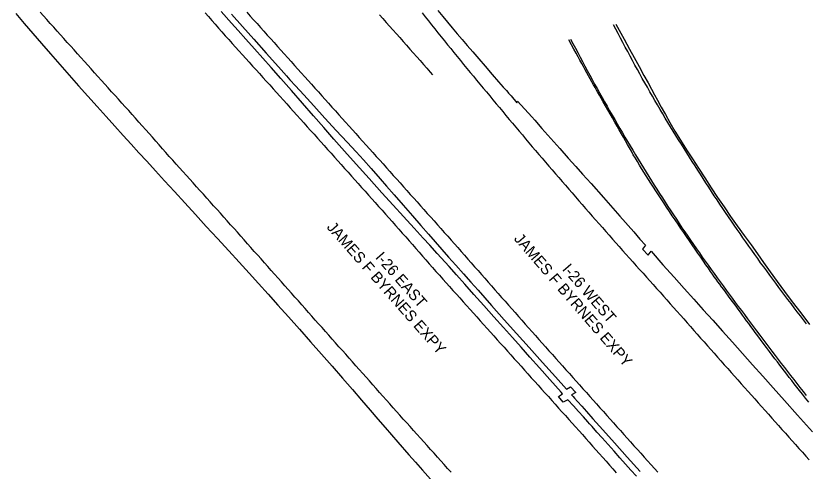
# Model space of a CAD drawing. Extents: x 1948091 to 1975253, y 787267 to 823306.
# Drawn here: x 1967304 to 1967691, y 800434.1 to 800657.3 of the extents above; entities that cross this region are included whole.
import ezdxf

# ---------------------------------------------------------------- set-up
doc = ezdxf.new("R2010")
doc.units = 0
for name, color, linetype in [('RD_EX_Pavement_Markings', 7, 'Continuous'), ('RD_EX_Road', 7, 'Continuous'), ('RD_TX_RoadID', 7, 'Continuous')]:
    doc.layers.add(name, color=color, linetype=linetype)

msp = doc.modelspace()

# ---------------------------------------------------------------- linework, layer by layer
at = {"layer": 'RD_EX_Pavement_Markings'}
for points in [[(1967517.07, 800433.59), (1967515.4, 800435.45), (1967513.73, 800437.31), (1967512.06, 800439.16), (1967510.39, 800441.02), (1967508.73, 800442.88), (1967507.06, 800444.74), (1967505.39, 800446.6), (1967503.72, 800448.46), (1967502.05, 800450.32), (1967500.38, 800452.17), (1967498.71, 800454.03), (1967497.04, 800455.89), (1967495.38, 800457.75), (1967493.71, 800459.61), (1967492.04, 800461.47), (1967490.37, 800463.33), (1967488.71, 800465.19), (1967487.06, 800467.06), (1967485.4, 800468.93), (1967483.74, 800470.8), (1967482.08, 800472.67), (1967480.43, 800474.54), (1967478.77, 800476.41), (1967477.11, 800478.28), (1967475.45, 800480.14), (1967473.8, 800482.01), (1967472.14, 800483.88), (1967470.48, 800485.75), (1967468.82, 800487.62), (1967467.17, 800489.49), (1967465.51, 800491.36), (1967463.85, 800493.22), (1967462.19, 800495.09), (1967460.53, 800496.96), (1967458.88, 800498.83), (1967457.22, 800500.7), (1967455.56, 800502.57), (1967453.9, 800504.43), (1967452.25, 800506.3), (1967450.59, 800508.17), (1967448.93, 800510.04), (1967447.27, 800511.91), (1967445.61, 800513.78), (1967443.96, 800515.64), (1967442.3, 800517.51), (1967440.64, 800519.38), (1967438.98, 800521.25), (1967437.32, 800523.12), (1967435.67, 800524.99), (1967434.01, 800526.85), (1967432.35, 800528.72), (1967430.69, 800530.59), (1967429.04, 800532.46), (1967427.38, 800534.33), (1967425.72, 800536.2), (1967424.06, 800538.07), (1967422.41, 800539.93), (1967420.75, 800541.8), (1967419.09, 800543.67), (1967417.43, 800545.54), (1967415.78, 800547.41), (1967414.12, 800549.28), (1967412.46, 800551.15), (1967410.8, 800553.01), (1967409.14, 800554.88), (1967407.49, 800556.75), (1967405.83, 800558.62), (1967404.17, 800560.49), (1967402.5, 800562.34), (1967400.83, 800564.2), (1967399.16, 800566.06), (1967397.48, 800567.91), (1967395.81, 800569.77), (1967394.14, 800571.63), (1967392.47, 800573.49), (1967390.8, 800575.34), (1967389.13, 800577.2), (1967387.46, 800579.06), (1967385.79, 800580.91), (1967384.12, 800582.77), (1967382.45, 800584.63), (1967380.78, 800586.49), (1967379.11, 800588.35), (1967377.46, 800590.22), (1967375.81, 800592.1), (1967374.15, 800593.97), (1967372.5, 800595.84), (1967370.85, 800597.72), (1967369.2, 800599.59), (1967367.55, 800601.46), (1967365.89, 800603.34), (1967364.24, 800605.21), (1967362.58, 800607.08), (1967360.91, 800608.93), (1967359.23, 800610.79), (1967357.56, 800612.64), (1967355.89, 800614.5), (1967354.21, 800616.35), (1967352.54, 800618.21), (1967350.87, 800620.07), (1967349.2, 800621.92), (1967347.52, 800623.78), (1967345.85, 800625.63), (1967344.18, 800627.49), (1967342.51, 800629.34), (1967340.84, 800631.21), (1967339.17, 800633.07), (1967337.51, 800634.93), (1967335.84, 800636.79), (1967334.17, 800638.65), (1967332.51, 800640.51), (1967330.84, 800642.37), (1967329.17, 800644.23), (1967327.51, 800646.1), (1967325.84, 800647.96), (1967324.17, 800649.82), (1967322.51, 800651.68), (1967320.84, 800653.54), (1967319.17, 800655.39), (1967317.49, 800657.25), (1967315.82, 800659.11)], [(1967396.61, 800658.72), (1967398.26, 800656.85), (1967399.92, 800654.99), (1967401.58, 800653.12), (1967403.24, 800651.25), (1967404.89, 800649.38), (1967406.55, 800647.51), (1967408.21, 800645.64), (1967409.87, 800643.77), (1967411.53, 800641.91), (1967413.21, 800640.06), (1967414.88, 800638.2), (1967416.56, 800636.35), (1967418.23, 800634.49), (1967419.9, 800632.64), (1967421.58, 800630.79), (1967423.25, 800628.93), (1967424.93, 800627.08), (1967426.6, 800625.22), (1967428.28, 800623.37), (1967429.95, 800621.51), (1967431.62, 800619.66), (1967433.3, 800617.8), (1967434.96, 800615.94), (1967436.63, 800614.09), (1967438.3, 800612.23), (1967439.97, 800610.37), (1967441.64, 800608.51), (1967443.31, 800606.65), (1967444.97, 800604.79), (1967446.64, 800602.93), (1967448.31, 800601.07), (1967449.98, 800599.21), (1967451.65, 800597.35), (1967453.31, 800595.49), (1967454.98, 800593.63), (1967456.65, 800591.77), (1967458.32, 800589.91), (1967459.98, 800588.05), (1967461.65, 800586.19), (1967463.31, 800584.33), (1967464.98, 800582.46), (1967466.64, 800580.6), (1967468.31, 800578.74), (1967469.97, 800576.88), (1967471.64, 800575.01), (1967473.3, 800573.15), (1967474.97, 800571.29), (1967476.63, 800569.43), (1967478.29, 800567.57), (1967479.96, 800565.7), (1967481.62, 800563.84), (1967483.29, 800561.98), (1967484.95, 800560.12), (1967486.61, 800558.25), (1967488.26, 800556.37), (1967489.91, 800554.5), (1967491.56, 800552.62), (1967493.21, 800550.74), (1967494.86, 800548.87), (1967496.51, 800546.99), (1967498.15, 800545.11), (1967499.8, 800543.24), (1967501.45, 800541.36), (1967503.1, 800539.49), (1967504.75, 800537.61), (1967506.4, 800535.73), (1967508.05, 800533.86), (1967509.7, 800531.98), (1967511.36, 800530.12), (1967513.03, 800528.26), (1967514.7, 800526.4), (1967516.36, 800524.54), (1967518.03, 800522.68), (1967519.7, 800520.82), (1967521.36, 800518.96), (1967523.03, 800517.1), (1967524.7, 800515.24), (1967526.36, 800513.37), (1967528.03, 800511.51), (1967529.7, 800509.65), (1967531.36, 800507.79), (1967533.03, 800505.93), (1967534.7, 800504.07), (1967536.37, 800502.21), (1967538.03, 800500.35), (1967539.7, 800498.5), (1967541.37, 800496.64), (1967543.04, 800494.78), (1967544.7, 800492.92), (1967546.37, 800491.06), (1967548.04, 800489.2), (1967549.71, 800487.34), (1967551.37, 800485.48), (1967553.04, 800483.62), (1967554.71, 800481.76), (1967556.38, 800479.9), (1967558.05, 800478.04), (1967559.71, 800476.18), (1967561.38, 800474.32), (1967563.05, 800472.46), (1967564.72, 800470.6), (1967566.39, 800468.74), (1967568.05, 800466.88), (1967569.72, 800465.02), (1967571.39, 800463.16), (1967573.06, 800461.3), (1967574.73, 800459.44), (1967576.39, 800457.59), (1967578.06, 800455.73), (1967579.73, 800453.86), (1967581.38, 800451.99), (1967583.04, 800450.13), (1967584.7, 800448.26), (1967586.36, 800446.39), (1967588.02, 800444.53), (1967589.68, 800442.66), (1967591.34, 800440.79), (1967593, 800438.92), (1967594.66, 800437.06), (1967596.32, 800435.19), (1967597.97, 800433.32)], [(1967417.08, 800659.03), (1967418.74, 800657.16), (1967420.41, 800655.3), (1967422.08, 800653.44), (1967423.75, 800651.58), (1967425.41, 800649.72), (1967427.08, 800647.86), (1967428.75, 800646), (1967430.41, 800644.14), (1967432.08, 800642.28), (1967433.75, 800640.42), (1967435.42, 800638.56), (1967437.08, 800636.7), (1967438.75, 800634.84), (1967440.42, 800632.98), (1967442.08, 800631.12), (1967443.75, 800629.25), (1967445.42, 800627.4), (1967447.09, 800625.54), (1967448.76, 800623.68), (1967450.42, 800621.82), (1967452.09, 800619.96), (1967453.76, 800618.1), (1967455.43, 800616.24), (1967457.1, 800614.38), (1967458.77, 800612.52), (1967460.43, 800610.66), (1967462.1, 800608.8), (1967463.77, 800606.94), (1967465.44, 800605.08), (1967467.11, 800603.22), (1967468.78, 800601.37), (1967470.45, 800599.51), (1967472.11, 800597.65), (1967473.78, 800595.79), (1967475.45, 800593.93), (1967477.12, 800592.07), (1967478.79, 800590.21), (1967480.46, 800588.35), (1967482.13, 800586.49), (1967483.8, 800584.64), (1967485.46, 800582.78), (1967487.13, 800580.92), (1967488.8, 800579.06), (1967490.47, 800577.2), (1967492.14, 800575.34), (1967493.8, 800573.48), (1967495.47, 800571.62), (1967497.13, 800569.76), (1967498.8, 800567.9), (1967500.47, 800566.03), (1967502.13, 800564.17), (1967503.8, 800562.31), (1967505.46, 800560.45), (1967507.13, 800558.59), (1967508.8, 800556.73), (1967510.46, 800554.87), (1967512.13, 800553.01), (1967513.78, 800551.13), (1967515.43, 800549.26), (1967517.08, 800547.38), (1967518.73, 800545.51), (1967520.38, 800543.63), (1967522.03, 800541.76), (1967523.68, 800539.88), (1967525.33, 800538.01), (1967526.98, 800536.13), (1967528.63, 800534.25), (1967530.28, 800532.38), (1967531.93, 800530.5), (1967533.58, 800528.63), (1967535.23, 800526.75), (1967536.88, 800524.88), (1967538.54, 800523.01), (1967540.19, 800521.14), (1967541.84, 800519.27), (1967543.5, 800517.39), (1967545.15, 800515.52), (1967546.81, 800513.65), (1967548.46, 800511.78), (1967550.11, 800509.9), (1967551.77, 800508.03), (1967553.42, 800506.16), (1967555.07, 800504.29), (1967556.73, 800502.42), (1967558.38, 800500.54), (1967560.03, 800498.67), (1967561.7, 800496.81), (1967563.36, 800494.94), (1967565.02, 800493.08), (1967566.69, 800491.22), (1967568.35, 800489.36), (1967570.02, 800487.49), (1967571.68, 800485.63), (1967573.35, 800483.77), (1967575.01, 800481.91), (1967576.68, 800480.04), (1967578.34, 800478.18), (1967580.01, 800476.32), (1967581.67, 800474.46), (1967583.34, 800472.59), (1967585, 800470.73), (1967586.66, 800468.87), (1967588.33, 800467.01), (1967589.99, 800465.14), (1967591.66, 800463.28), (1967593.32, 800461.42), (1967594.99, 800459.56), (1967596.65, 800457.69), (1967598.32, 800455.83), (1967599.98, 800453.97), (1967601.65, 800452.11), (1967603.32, 800450.25), (1967604.99, 800448.4), (1967606.66, 800446.54), (1967608.33, 800444.68), (1967610, 800442.83), (1967611.68, 800440.97), (1967613.35, 800439.12), (1967615.02, 800437.26), (1967616.69, 800435.4), (1967618.36, 800433.55)], [(1967482.02, 800657.8), (1967483.68, 800655.93), (1967485.34, 800654.06), (1967486.99, 800652.19), (1967488.65, 800650.32), (1967490.31, 800648.46), (1967491.97, 800646.59), (1967493.62, 800644.72), (1967495.28, 800642.85), (1967496.94, 800640.98), (1967498.59, 800639.11), (1967500.25, 800637.24), (1967501.9, 800635.36), (1967503.54, 800633.48), (1967505.18, 800631.6), (1967506.83, 800629.71), (1967508.06, 800628.31)], [(1967502.89, 800658.73), (1967504.44, 800656.77), (1967505.99, 800654.81), (1967507.54, 800652.85), (1967509.09, 800650.89), (1967510.65, 800648.94), (1967512.22, 800647), (1967513.8, 800645.06), (1967515.37, 800643.12), (1967516.95, 800641.18), (1967518.52, 800639.24), (1967520.09, 800637.3), (1967521.67, 800635.36), (1967523.24, 800633.42), (1967524.83, 800631.49), (1967526.42, 800629.56), (1967528.02, 800627.64), (1967529.61, 800625.72), (1967531.2, 800623.79), (1967532.8, 800621.87), (1967534.39, 800619.95), (1967535.99, 800618.02), (1967537.58, 800616.1), (1967539.18, 800614.18), (1967540.77, 800612.26), (1967542.37, 800610.34), (1967543.98, 800608.43), (1967545.58, 800606.51), (1967547.19, 800604.6), (1967548.79, 800602.68), (1967550.39, 800600.77), (1967552, 800598.85), (1967553.6, 800596.94), (1967555.2, 800595.02), (1967556.81, 800593.11), (1967558.43, 800591.21), (1967560.06, 800589.32), (1967561.7, 800587.43), (1967563.33, 800585.54), (1967564.97, 800583.65), (1967566.6, 800581.76), (1967568.24, 800579.87), (1967569.87, 800577.98), (1967571.5, 800576.1), (1967573.14, 800574.21), (1967574.77, 800572.32), (1967576.41, 800570.43), (1967578.05, 800568.55), (1967579.69, 800566.66), (1967581.32, 800564.78), (1967582.96, 800562.89), (1967584.6, 800561), (1967586.23, 800559.12), (1967587.88, 800557.24), (1967589.53, 800555.37), (1967591.18, 800553.49), (1967592.83, 800551.62), (1967594.48, 800549.74), (1967596.13, 800547.87), (1967597.78, 800545.99), (1967599.43, 800544.12), (1967601.08, 800542.24), (1967602.74, 800540.38), (1967604.41, 800538.52), (1967606.08, 800536.66), (1967607.74, 800534.8), (1967609.41, 800532.94), (1967611.08, 800531.08), (1967612.74, 800529.21), (1967614.41, 800527.35), (1967616.08, 800525.49), (1967617.74, 800523.63), (1967619.41, 800521.77), (1967621.07, 800519.9), (1967622.73, 800518.03), (1967624.38, 800516.16), (1967626.04, 800514.29), (1967627.69, 800512.42), (1967629.35, 800510.55), (1967631, 800508.68), (1967632.66, 800506.81), (1967634.31, 800504.94), (1967635.97, 800503.07), (1967637.63, 800501.2), (1967639.28, 800499.33), (1967640.94, 800497.46), (1967642.59, 800495.59), (1967644.25, 800493.72), (1967645.9, 800491.85), (1967647.56, 800489.98), (1967649.22, 800488.11), (1967650.87, 800486.24), (1967652.53, 800484.37), (1967654.19, 800482.5), (1967655.86, 800480.64), (1967657.52, 800478.78), (1967659.18, 800476.91), (1967660.84, 800475.05), (1967662.51, 800473.18), (1967664.17, 800471.32), (1967665.83, 800469.45), (1967667.49, 800467.59), (1967669.16, 800465.73), (1967670.82, 800463.86), (1967672.48, 800462), (1967674.14, 800460.13), (1967675.81, 800458.27), (1967677.47, 800456.4), (1967679.13, 800454.54), (1967680.8, 800452.68), (1967682.46, 800450.81), (1967684.13, 800448.95), (1967685.79, 800447.09), (1967687.45, 800445.23), (1967689.12, 800443.37), (1967690.78, 800441.5), (1967692.45, 800439.64)], [(1967691.18, 800506.29), (1967689.65, 800508.25), (1967688.11, 800510.22), (1967686.59, 800512.21), (1967685.08, 800514.19), (1967683.56, 800516.18), (1967682.05, 800518.16), (1967680.53, 800520.15), (1967679.03, 800522.14), (1967677.55, 800524.15), (1967676.07, 800526.17), (1967674.59, 800528.18), (1967673.12, 800530.19), (1967671.64, 800532.2), (1967670.16, 800534.22), (1967668.68, 800536.23), (1967667.23, 800538.26), (1967665.79, 800540.3), (1967664.35, 800542.34), (1967662.9, 800544.37), (1967661.46, 800546.41), (1967660.02, 800548.45), (1967658.58, 800550.49), (1967657.14, 800552.53), (1967655.73, 800554.59), (1967654.33, 800556.66), (1967652.92, 800558.72), (1967651.52, 800560.78), (1967650.11, 800562.85), (1967648.73, 800564.93), (1967647.36, 800567.01), (1967645.99, 800569.1), (1967644.61, 800571.19), (1967643.24, 800573.27), (1967641.88, 800575.36), (1967640.54, 800577.47), (1967639.2, 800579.58), (1967637.86, 800581.69), (1967636.53, 800583.8), (1967635.19, 800585.91), (1967633.85, 800588.01), (1967632.52, 800590.12), (1967631.18, 800592.23), (1967629.84, 800594.34), (1967628.5, 800596.45), (1967627.17, 800598.56), (1967625.84, 800600.68), (1967624.55, 800602.82), (1967623.27, 800604.96), (1967621.98, 800607.1), (1967620.7, 800609.25), (1967619.44, 800611.4), (1967618.19, 800613.56), (1967616.93, 800615.72), (1967615.68, 800617.89), (1967614.45, 800620.06), (1967613.21, 800622.23), (1967611.98, 800624.4), (1967610.74, 800626.57), (1967609.53, 800628.75), (1967608.33, 800630.94), (1967607.13, 800633.13), (1967605.93, 800635.32), (1967604.73, 800637.51), (1967603.56, 800639.72), (1967602.4, 800641.93), (1967601.24, 800644.14), (1967600.07, 800646.35), (1967598.91, 800648.56), (1967597.74, 800650.77), (1967596.67, 800652.81)], [(1967575.61, 800645.84), (1967576.78, 800643.63), (1967577.95, 800641.42), (1967579.11, 800639.21), (1967580.27, 800637), (1967581.43, 800634.79), (1967582.59, 800632.58), (1967583.77, 800630.38), (1967584.96, 800628.18), (1967586.16, 800625.99), (1967587.36, 800623.8), (1967588.57, 800621.62), (1967589.8, 800619.44), (1967591.02, 800617.27), (1967592.25, 800615.09), (1967593.48, 800612.92), (1967594.72, 800610.75), (1967595.97, 800608.59), (1967597.22, 800606.42), (1967598.46, 800604.26), (1967599.71, 800602.1), (1967600.97, 800599.94), (1967602.24, 800597.79), (1967603.51, 800595.64), (1967604.78, 800593.49), (1967606.05, 800591.34), (1967607.33, 800589.19), (1967608.63, 800587.06), (1967609.94, 800584.93), (1967611.24, 800582.8), (1967612.55, 800580.67), (1967613.86, 800578.55), (1967615.18, 800576.43), (1967616.53, 800574.32), (1967617.87, 800572.22), (1967619.22, 800570.12), (1967620.57, 800568.01), (1967621.91, 800565.91), (1967623.28, 800563.82), (1967624.66, 800561.74), (1967626.03, 800559.65), (1967627.4, 800557.57), (1967628.78, 800555.48), (1967630.15, 800553.4), (1967631.57, 800551.34), (1967632.99, 800549.29), (1967634.4, 800547.23), (1967635.82, 800545.18), (1967637.24, 800543.12), (1967638.66, 800541.06), (1967640.11, 800539.03), (1967641.56, 800537), (1967643.01, 800534.97), (1967644.47, 800532.94), (1967645.92, 800530.91), (1967647.37, 800528.88), (1967648.85, 800526.87), (1967650.33, 800524.85), (1967651.8, 800522.84), (1967653.28, 800520.83), (1967654.76, 800518.81), (1967656.24, 800516.8), (1967657.73, 800514.8), (1967659.22, 800512.79), (1967660.71, 800510.79), (1967662.2, 800508.79), (1967663.7, 800506.79), (1967665.19, 800504.79), (1967666.69, 800502.79), (1967668.2, 800500.8), (1967669.71, 800498.81), (1967671.22, 800496.82), (1967672.73, 800494.83), (1967674.23, 800492.84), (1967675.74, 800490.85), (1967677.26, 800488.87), (1967678.78, 800486.89), (1967680.3, 800484.91), (1967681.82, 800482.92), (1967683.34, 800480.94), (1967684.86, 800478.96), (1967686.4, 800476.99), (1967687.94, 800475.03), (1967689.49, 800473.07), (1967691.04, 800471.11)]]:
    msp.add_lwpolyline(points, dxfattribs=at)
at = {"layer": 'RD_EX_Road'}
for points in [[(1967303.95, 800658.36), (1967308.08, 800653.55), (1967312.27, 800648.66), (1967316.54, 800643.69), (1967320.92, 800638.62), (1967325.43, 800633.46), (1967330.04, 800628.21), (1967334.68, 800622.97), (1967339.25, 800617.84), (1967343.73, 800612.84), (1967348.14, 800607.95), (1967352.42, 800603.22), (1967356.54, 800598.68), (1967360.48, 800594.33), (1967364.26, 800590.17), (1967368.11, 800585.94), (1967372.28, 800581.35), (1967376.78, 800576.41), (1967381.6, 800571.13), (1967386.66, 800565.59), (1967391.87, 800559.89), (1967397.24, 800554.05), (1967402.76, 800548.05), (1967408.21, 800542.12), (1967413.38, 800536.46), (1967418.27, 800531.09), (1967422.87, 800526), (1967427.46, 800520.89), (1967432.31, 800515.47), (1967437.43, 800509.74), (1967442.8, 800503.7), (1967448.25, 800497.55), (1967453.59, 800491.49), (1967458.8, 800485.53), (1967463.9, 800479.66), (1967468.76, 800474.03), (1967473.28, 800468.8), (1967477.45, 800463.97), (1967481.28, 800459.54), (1967484.8, 800455.47), (1967491.01, 800448.32), (1967496.46, 800442.1), (1967499.6, 800438.56), (1967503.12, 800434.6), (1967507.02, 800430.22)], [(1967607.81, 800431.6), (1967605.16, 800434.58), (1967602.49, 800437.59), (1967599.74, 800440.69), (1967596.89, 800443.88), (1967593.96, 800447.16), (1967591.11, 800450.35), (1967588.49, 800453.27), (1967586.11, 800455.93), (1967584.85, 800457.35), (1967583.98, 800458.32), (1967581.86, 800460.68), (1967579.54, 800463.26), (1967577.03, 800466.05), (1967574.31, 800469.06), (1967572.05, 800467.86), (1967569.68, 800470.7), (1967571.72, 800472), (1967571.01, 800472.81), (1967565.5, 800478.98), (1967560.39, 800484.7), (1967555.68, 800489.98), (1967551.37, 800494.81), (1967547.14, 800499.55), (1967542.69, 800504.55), (1967538.01, 800509.8), (1967533.1, 800515.32), (1967528.27, 800520.74), (1967523.84, 800525.71), (1967519.79, 800530.24), (1967516.13, 800534.32), (1967510.3, 800540.8), (1967506.64, 800544.83), (1967503.43, 800548.34), (1967498.95, 800553.24), (1967493.83, 800558.83), (1967488.72, 800564.43), (1967483.21, 800570.48), (1967476.91, 800577.47), (1967470.57, 800584.56), (1967464.93, 800590.95), (1967459.75, 800596.85), (1967454.79, 800602.5), (1967449.75, 800608.26), (1967444.35, 800614.46), (1967438.91, 800620.7), (1967433.75, 800626.58), (1967429.01, 800631.93), (1967424.86, 800636.58), (1967420.86, 800641.06), (1967416.58, 800645.87), (1967412.9, 800650), (1967409.59, 800653.72), (1967404.58, 800659.33)], [(1967409.51, 800658.04), (1967414.92, 800651.98), (1967420.48, 800645.76), (1967426.5, 800639.03), (1967432.61, 800632.18), (1967436.48, 800627.85), (1967438.21, 800625.92), (1967440.89, 800622.95), (1967444.94, 800618.49), (1967449.81, 800613.15), (1967455.3, 800607.12), (1967460.85, 800601.1), (1967466.25, 800595.31), (1967470.66, 800590.53), (1967474.16, 800586.67), (1967477.89, 800582.46), (1967482.33, 800577.36), (1967485.41, 800573.81), (1967489.17, 800569.5), (1967493.59, 800564.41), (1967498.14, 800559.18), (1967502.27, 800554.43), (1967506, 800550.16), (1967512.51, 800542.75), (1967515.87, 800538.94), (1967519.4, 800534.97), (1967523.1, 800530.83), (1967526.8, 800526.69), (1967530.33, 800522.72), (1967536.93, 800515.3), (1967543.12, 800508.33), (1967549.14, 800501.58), (1967555.29, 800494.71), (1967561.87, 800487.38), (1967568.19, 800480.33), (1967573.58, 800474.3), (1967573.68, 800474.19), (1967575.58, 800475.43), (1967578.16, 800472.67), (1967576.13, 800471.46), (1967576.88, 800470.64), (1967577.53, 800469.9), (1967579, 800468.22), (1967581.04, 800465.92), (1967583.35, 800463.31), (1967586.58, 800459.7), (1967591.36, 800454.34), (1967597.12, 800447.89), (1967603.31, 800440.97), (1967609.62, 800433.92)], [(1967510.56, 800659.84), (1967512.98, 800656.9), (1967515.3, 800654.09), (1967517.61, 800651.32), (1967519.99, 800648.49), (1967522.45, 800645.61), (1967524.98, 800642.67), (1967527.67, 800639.56), (1967530.61, 800636.18), (1967533.78, 800632.52), (1967537.2, 800628.58), (1967540.33, 800624.98), (1967542.65, 800622.32), (1967544.15, 800620.61), (1967544.84, 800619.83), (1967545.21, 800619.43), (1967545.76, 800618.81), (1967546.48, 800617.98), (1967549.35, 800614.65), (1967549.69, 800615.45), (1967556.57, 800607.69), (1967558.03, 800606.04), (1967561.58, 800602.03), (1967565.87, 800597.2), (1967570.33, 800592.16), (1967574.42, 800587.57), (1967578.14, 800583.4), (1967581.5, 800579.67), (1967585.63, 800575.05), (1967591.69, 800568.2), (1967599.67, 800559.12), (1967606.5, 800551.32), (1967609.58, 800547.82), (1967612.26, 800544.77), (1967610.82, 800542.81), (1967613.56, 800539.94), (1967615.02, 800541.84), (1967620.85, 800535.21), (1967626.25, 800529.21), (1967631.3, 800523.59), (1967636.01, 800518.34), (1967640.59, 800513.23), (1967645.26, 800508.01), (1967650.01, 800502.7), (1967654.85, 800497.28), (1967659.75, 800491.78), (1967664.71, 800486.22), (1967669.71, 800480.61), (1967674.77, 800474.95), (1967680.3, 800468.76), (1967686.72, 800461.56), (1967694.04, 800453.36)], [(1967597.82, 800653.2), (1967601.78, 800645.88), (1967604.49, 800640.9), (1967606.69, 800636.86), (1967609.14, 800632.38), (1967611.52, 800628.02), (1967613.54, 800624.34), (1967615.23, 800621.23), (1967616.65, 800618.58), (1967618.12, 800615.87), (1967619.94, 800612.56), (1967622.02, 800608.86), (1967624.26, 800604.97), (1967626.72, 800600.8), (1967629.47, 800596.27), (1967632.36, 800591.62), (1967635.26, 800587.09), (1967638.21, 800582.55), (1967641.27, 800577.81), (1967644.4, 800573.02), (1967647.55, 800568.28), (1967650.73, 800563.6), (1967653.92, 800558.98), (1967657.2, 800554.35), (1967660.61, 800549.61), (1967663.98, 800544.97), (1967667.1, 800540.6), (1967670.15, 800536.28), (1967673.33, 800531.78), (1967676.69, 800527.09), (1967680.28, 800522.22), (1967684.14, 800517.09), (1967688.29, 800511.61), (1967692.64, 800505.93)], [(1967692.3, 800467.87), (1967690.65, 800469.93), (1967689.11, 800471.85), (1967687.68, 800473.65), (1967686.37, 800475.32), (1967685.12, 800476.91), (1967683.9, 800478.48), (1967682.69, 800480.03), (1967681.5, 800481.55), (1967680.33, 800483.06), (1967679.17, 800484.58), (1967678.02, 800486.09), (1967676.88, 800487.6), (1967675.69, 800489.18), (1967674.39, 800490.9), (1967672.98, 800492.76), (1967671.46, 800494.76), (1967669.95, 800496.76), (1967668.55, 800498.64), (1967667.25, 800500.38), (1967666.07, 800501.99), (1967664.96, 800503.51), (1967663.88, 800504.98), (1967662.83, 800506.41), (1967661.81, 800507.8), (1967660.8, 800509.18), (1967659.78, 800510.58), (1967658.75, 800512), (1967657.7, 800513.44), (1967656.61, 800514.94), (1967655.47, 800516.5), (1967654.26, 800518.13), (1967653, 800519.84), (1967651.76, 800521.51), (1967650.62, 800523.04), (1967649.58, 800524.43), (1967648.65, 800525.69), (1967647.76, 800526.89), (1967646.88, 800528.12), (1967645.98, 800529.37), (1967645.09, 800530.64), (1967644.14, 800532.01), (1967643.08, 800533.53), (1967641.91, 800535.22), (1967640.64, 800537.06), (1967639.31, 800539), (1967637.96, 800540.96), (1967636.58, 800542.95), (1967635.19, 800544.97), (1967633.79, 800547), (1967632.39, 800549.03), (1967631, 800551.06), (1967629.61, 800553.09), (1967628.23, 800555.14), (1967626.83, 800557.2), (1967625.42, 800559.29), (1967623.99, 800561.4), (1967622.58, 800563.5), (1967621.22, 800565.54), (1967619.9, 800567.54), (1967618.62, 800569.49), (1967617.38, 800571.4), (1967616.16, 800573.29), (1967614.95, 800575.16), (1967613.76, 800577), (1967612.6, 800578.81), (1967611.48, 800580.59), (1967610.39, 800582.35), (1967609.35, 800584.07), (1967608.33, 800585.78), (1967607.32, 800587.48), (1967606.33, 800589.17), (1967605.36, 800590.85), (1967604.39, 800592.54), (1967603.42, 800594.24), (1967602.45, 800595.97), (1967601.47, 800597.71), (1967600.47, 800599.49), (1967599.44, 800601.34), (1967598.37, 800603.24), (1967597.26, 800605.21), (1967596.13, 800607.21), (1967595, 800609.21), (1967593.86, 800611.21), (1967592.72, 800613.22), (1967591.63, 800615.12), (1967590.66, 800616.82), (1967589.79, 800618.32), (1967589.03, 800619.63), (1967588.31, 800620.86), (1967587.57, 800622.15), (1967586.81, 800623.49), (1967586.02, 800624.9), (1967585.22, 800626.34), (1967584.41, 800627.81), (1967583.6, 800629.3), (1967582.77, 800630.8), (1967581.93, 800632.34), (1967581.06, 800633.91), (1967580.17, 800635.51), (1967579.26, 800637.15), (1967578.29, 800638.92), (1967577.21, 800640.91), (1967576.02, 800643.12), (1967574.73, 800645.54)]]:
    msp.add_lwpolyline(points, dxfattribs=at)

# ---------------------------------------------------------------- texts
at = {"layer": 'RD_TX_RoadID'}
for s, rotation, p in [('JAMES F BYRNES EXPY', 311.3041, (1967455.92, 800553.45)), ('JAMES F BYRNES EXPY', 310.8819, (1967547.56, 800547.82)), ('I-26 EAST', 311.3041, (1967479.68, 800538.67)), ('I-26 WEST', 310.8819, (1967571.21, 800532.87))]:
    msp.add_text(s, height=5.4, rotation=rotation, dxfattribs=at).set_placement(p)

doc.saveas('drawing.dxf')
